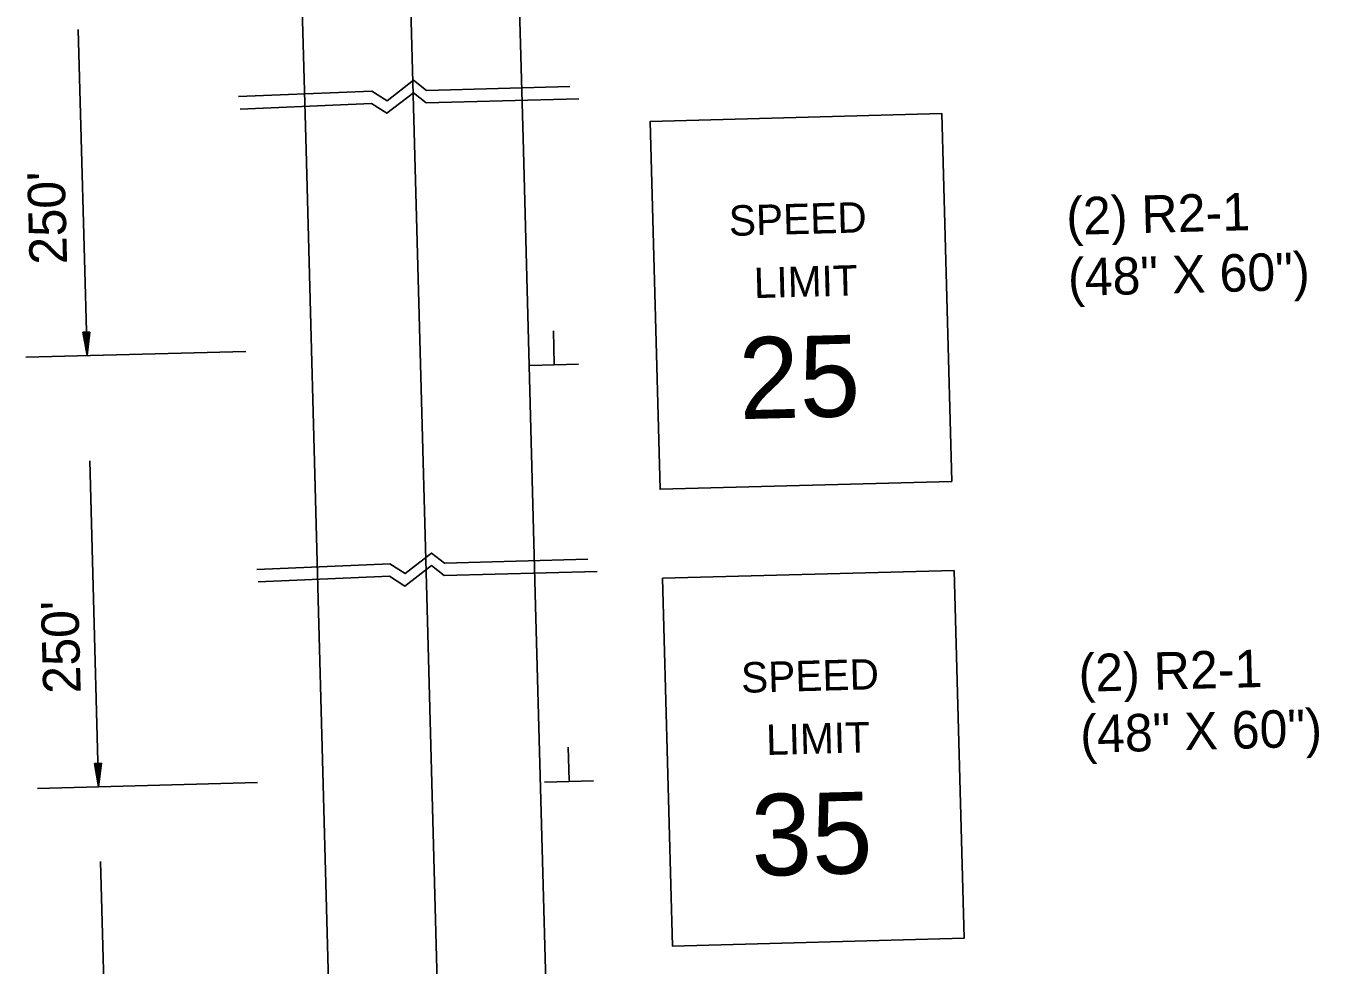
# Model space of a CAD drawing. Extents: x 1929624 to 1932072, y 596315 to 605954.
# Drawn here: x 1930902.5 to 1931109.4, y 596499.2 to 596649.5 of the extents above; entities that cross this region are included whole.
import ezdxf

# ---------------------------------------------------------------- set-up
doc = ezdxf.new("R2010")
doc.units = 0
doc.layers.add('Default', color=7, linetype='Continuous')

msp = doc.modelspace()

# ---------------------------------------------------------------- linework, layer by layer
at = {"layer": 'Default'}
for p, q in [((1930947.32, 596629.63), (1930945.65, 596691.59)), ((1930964.68, 596630.56), (1930963.04, 596691.72)), ((1930982.05, 596631.49), (1930980.43, 596691.84)), ((1930912.27, 596596.7), (1930910.87, 596648.87)), ((1930984.06, 596556.66), (1930982.05, 596631.49)), ((1930949.3, 596555.72), (1930947.32, 596629.63)), ((1930966.68, 596556.19), (1930964.68, 596630.56)), ((1930912.73, 596600.46), (1930911.61, 596600.43)), ((1930911.61, 596600.43), (1930912.27, 596596.7)), ((1930911.7, 596600.44), (1930912.25, 596597.33)), ((1930911.79, 596600.44), (1930912.23, 596597.97)), ((1930911.89, 596600.44), (1930912.22, 596598.59)), ((1930911.98, 596600.44), (1930912.2, 596599.23)), ((1930912.08, 596600.45), (1930912.18, 596599.86)), ((1930912.26, 596600.45), (1930912.18, 596599.86)), ((1930912.35, 596600.45), (1930912.2, 596599.23)), ((1930912.45, 596600.46), (1930912.22, 596598.59)), ((1930912.54, 596600.46), (1930912.23, 596597.97)), ((1930912.64, 596600.46), (1930912.25, 596597.33)), ((1930912.73, 596600.46), (1930912.27, 596596.7)), ((1930987.05, 596595.33), (1930986.91, 596600.67)), ((1930902.48, 596596.44), (1930937.68, 596597.38)), ((1930990.94, 596595.32), (1930983.12, 596595.11)), ((1930914.12, 596527.72), (1930912.72, 596579.89)), ((1930968.53, 596487.21), (1930966.68, 596556.19)), ((1930985.91, 596487.68), (1930984.06, 596556.66)), ((1930951.15, 596486.74), (1930949.3, 596555.72)), ((1930989.4, 596528.7), (1930989.26, 596534.04)), ((1930914.58, 596531.48), (1930913.46, 596531.45)), ((1930913.46, 596531.45), (1930914.12, 596527.72)), ((1930913.55, 596531.46), (1930914.1, 596528.35)), ((1930913.65, 596531.46), (1930914.09, 596528.99)), ((1930913.74, 596531.46), (1930914.07, 596529.61)), ((1930913.84, 596531.46), (1930914.05, 596530.25)), ((1930913.93, 596531.47), (1930914.04, 596530.88)), ((1930914.11, 596531.47), (1930914.04, 596530.88)), ((1930914.2, 596531.47), (1930914.05, 596530.25)), ((1930914.3, 596531.48), (1930914.07, 596529.61)), ((1930914.39, 596531.48), (1930914.09, 596528.99)), ((1930914.49, 596531.48), (1930914.1, 596528.35)), ((1930914.58, 596531.48), (1930914.12, 596527.72)), ((1930904.33, 596527.46), (1930939.53, 596528.4)), ((1930993.3, 596528.69), (1930985.48, 596528.48)), ((1930915.84, 596463.58), (1930914.44, 596515.75))]:
    msp.add_line(p, q, dxfattribs=at)
for points in [[(1930936.53, 596638.13), (1930957.82, 596639.03), (1930960.28, 596637.47), (1930964.52, 596640.75), (1930966.57, 596639.14), (1930989.53, 596639.75)], [(1930936.78, 596636.14), (1930957.79, 596637.03), (1930960.25, 596635.47), (1930964.49, 596638.75), (1930966.54, 596637.14), (1930990.98, 596637.79)], [(1930939.43, 596562.5), (1930960.72, 596563.4), (1930963.18, 596561.84), (1930967.42, 596565.12), (1930969.46, 596563.51), (1930992.42, 596564.12)], [(1930939.67, 596560.51), (1930960.69, 596561.4), (1930963.15, 596559.84), (1930967.39, 596563.12), (1930969.43, 596561.51), (1930993.88, 596562.16)]]:
    msp.add_lwpolyline(points, dxfattribs=at)
for points in [[(1931049.08, 596635.43), (1931050.66, 596576.58), (1931003.97, 596575.32), (1931002.39, 596634.17)], [(1931051.05, 596562.34), (1931052.63, 596503.49), (1931005.94, 596502.24), (1931004.36, 596561.09)]]:
    msp.add_lwpolyline(points, close=True, dxfattribs=at)

# ---------------------------------------------------------------- texts
for s, height, rotation, p in [("250'", 6, 91.5377, (1930909.09, 596611.35)), ('(2) R2-1', 6, 1.5377, (1931069.05, 596615.99)), ('SPEED', 4.865, 1.5377, (1931015.04, 596615.84)), ('(48" X 60")', 6, 1.5377, (1931069.32, 596606.22)), ('LIMIT', 4.865, 1.5377, (1931019.04, 596605.89)), ('25', 13.039, 1.5377, (1931016.73, 596586.52)), ("250'", 6, 91.5377, (1930911.27, 596542.69)), ('SPEED', 4.865, 1.5377, (1931017, 596542.75)), ('(2) R2-1', 6, 1.5377, (1931071.02, 596542.9)), ('(48" X 60")', 6, 1.5377, (1931071.28, 596533.13)), ('LIMIT', 4.865, 1.5377, (1931021, 596532.8)), ('35', 13.039, 1.5377, (1931018.7, 596513.43))]:
    msp.add_text(s, height=height, rotation=rotation, dxfattribs=at).set_placement(p)

doc.saveas('drawing.dxf')
